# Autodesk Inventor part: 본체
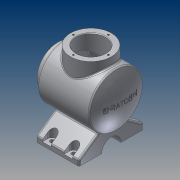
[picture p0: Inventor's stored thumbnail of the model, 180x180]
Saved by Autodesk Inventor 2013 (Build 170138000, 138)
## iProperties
Created: 2017-04
Part Number: 본체
Material: 알루미늄 6061
Document SubType Name: Modeling
Designer: Administrator
Density: 2.71 g/cm^3
Mass: 1670.75 g
Surface Area: 1066.86 cm^2
Volume: 616.514 cm^3
Author: Administrator
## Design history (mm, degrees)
sketch "스케치1"
  geometry: L1 (-62, 82)-(58, 82); L2 (-50, 132)-(46.336, 132); L3 (-50, 132)-(-50, 120); L4 (-50, 120)-(-62, 120); L5 (-62, 120)-(-62, 82); L6 (39.916, 122)-(-40, 122); L7 (-62, 109)-(-40, 109); L8 (-40, 122)-(-40, 109); A1 r 113 centre (-55, 82) between (58, 82) and (46.336, 132); A2 r 103 centre (-55, 82) between (48, 82) and (39.916, 122); 1 further point
  constraints: 16 end point, 4 point on circle, 3 perpendicular, 3 point on line, 2 centre point, 2 parallel, 1 horizontal
  dimensions: "d1" = 120 distance of L1.start L1.end; "d3" = 58 horizontal distance of point (0, 0) L1.end; "d5" = 113 radius of A1; "d6" = 82 vertical distance of point (0, 0) L1.end; "d7" = 100 diameter of L2 L1; "d8" = 108 horizontal distance of L2.start L1.end; "d9" = 76 diameter of L4 L1; "d10" = 10 distance between parallel lines of L6 L2; "d12" = 10 radial gap between concentric circles of A1 A2; "d13" = 54 diameter of L7 L1; "d14" = 22 distance of L7.start L7.end
revolve "회전1" sketch "스케치1" stored, may be unused: angle "d15" = 90 deg
node "작업 평면1"
sketch "스케치2"
  geometry: L1 (-60, -82)-(-60, -72); L2 (60, -82)-(60, -72); L3 (0, -82)-(0, 0); L4 (-60, -72)-(-21.584, -45.101); L5 (60, -72)-(21.584, -45.101); L6 (-60, -82)-(-18, -82); L7 (60, -82)-(18, -82); C1 r 27 at (0, 0) reference; A1 r 50 centre (0, 0) between (-21.584, -45.101) and (21.584, -45.101) reference; A2 r 18 centre (0, -82) between (18, -82) and (-18, -82)
  constraints: 14 end point, 4 point on circle, 3 parallel, 2 horizontal alignment, 1 centre point, 1 coincident, 1 collinear, 1 perpendicular, 1 vertical, 2 other
  dimensions: "d18" = 120 distance of L1.start L2.start; "d20" = 55 deg angle of L1 L4; "d21" = 18 radius of A2; "d98" = 10 distance of L2.start L2.end
extrude "돌출1" join sketch "스케치2" distance "d22" = 80; taper "d23" = 0 deg
node "작업 평면2"
sketch "스케치3"
  geometry: L1 (-38, 60)-(42, 60) reference; L2 (42, 60)-(42, 16.971) reference; L3 (42, 16.971)-(-38, 16.971) reference; L4 (-38, 16.971)-(-38, 60) reference; L5 (42, -60)-(-38, -60) reference; L6 (-38, -60)-(-38, -16.971) reference; L7 (-38, -16.971)-(42, -16.971) reference; L8 (42, -16.971)-(42, -60) reference; L9 (30, 50)-(30, 60); L10 (14, 50)-(14, 60); A1 r 8 centre (22, 50) between (30, 50) and (14, 50); 1 further point
  constraints: 4 end point, 2 parallel, 2 point on circle, 2 point on line, 2 tangent, 1 centre point
  dimensions: "d25" = 8 radius of A1; "d27" = 20 distance from line of A1.centre L2; "d28" = 10 distance from line of A1.centre L1
extrude "돌출2" cut sketch "스케치3" stored distance "d29" = 80; taper "d30" = 0 deg
hole "구멍1" diameter "d36" = 8; stored, may be unused: countersink angle "d40" = 90 deg, drill point angle "d42" = 118 deg; dims "d34" = 10, "d35" = 10, "d37" = 6, "d38" = 4, "d39" = 2, "d41" = 8
node "작업 평면3"
sketch "스케치4"
  geometry: C1 r 38 at (0, 0); 1 further point
  constraints: 1 centre point, 1 coincident
  dimensions: "d50" = 76 diameter of C1
extrude "돌출3" join sketch "스케치4" stored distance "d52" = 80; taper "d53" = 0 deg
hole "구멍2" diameter "d56" = 54; stored, may be unused: countersink angle "d60" = 90 deg, drill point angle "d62" = 0 deg; dims "d54" = 10, "d55" = 10, "d57" = 6, "d58" = 4, "d59" = 2, "d61" = 58.25
node "작업 평면4"
sketch "스케치5"
  geometry: C1 r 50 at (0, 0) reference; 2 further points
  constraints: 1 coincident, 1 other
feature "엠보싱1" sketch "스케치5" dims "d1" = 120, "d3" = 58, "d5" = 113, "d6" = 82, "d7" = 100, "d8" = 108, "d9" = 76, "d10" = 10, "d12" = 10, "d13" = 54, "d14" = 22, "d63" = 0.5, "d64" = 0
sketch "스케치6" dims "d65" = 65
  geometry: C1 r 38 at (0, 0) reference; C2 r 27 at (0, 0) reference; 3 further points
  constraints: 2 vertical alignment, 1 coincident, 2 other
hole "구멍3" sketch "스케치6" at (0, 32.5) diameter "d67" = 3.242; stored, may be unused: countersink angle "d71" = 90 deg, drill point angle "d73" = 118 deg; dims "d68" = 8, "d69" = 4, "d70" = 2, "d72" = 10
sketch "스케치7" dims "d77" = 65
  geometry: C1 r 27 at (0, 0) reference; C2 r 38 at (0, 0) reference; 2 further points
  constraints: 2 vertical alignment, 1 coincident, 2 other
hole "구멍4" sketch "스케치7" at (0, 32.5) diameter "d79" = 3.242; stored, may be unused: countersink angle "d83" = 90 deg, drill point angle "d85" = 118 deg; dims "d80" = 8, "d81" = 4, "d82" = 2, "d84" = 10
fillet "모깎기1" dims "d93" = 3
chamfer "모따기1" distance "d94" = 1; stored, may be unused: second distance "d95" = 2, angle "d96" = 45 deg
fillet "모깎기2" dims "d97" = 3
node "솔리드1"
pattern_linear "직사각형 패턴1" dims "d33" = 40
mirror "대칭1"
pattern_linear "직사각형 패턴2" dims "d45" = 40
pattern_circular "원형 패턴1" dims angle "d75" = 360 deg
pattern_circular "원형 패턴2" dims angle "d87" = 360 deg
node "절단 모서리 투영1"
node "절단 모서리 투영2"
other parameters: "d16" = -8, "d24" = 6, "d49" = 147, "d89" = 0.5, "d90" = 2, "d91" = 0
